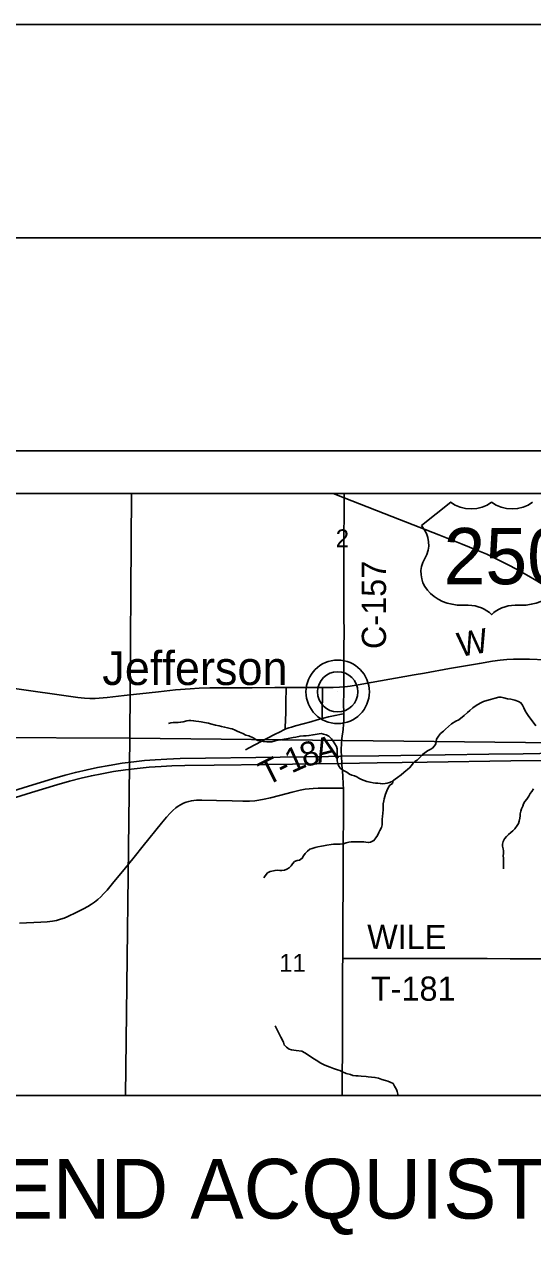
# Model space of a CAD drawing. Extents: x 0 to 34, y 0 to 22.
# Drawn here: x 3.534 to 4.726, y 19.142 to 22 of the extents above; entities that cross this region are included whole.
import ezdxf

# ---------------------------------------------------------------- set-up
doc = ezdxf.new("R2010")
doc.units = 0
for name, color, linetype in [('GM_X_County_Road', 7, 'Continuous'), ('GM_X_County_Road_Text', 7, 'Continuous'), ('GM_X_Minor_River', 7, 'Continuous'), ('GM_X_Section', 7, 'Continuous'), ('GM_X_Section_Text', 7, 'Continuous'), ('GM_X_Township_Road', 7, 'Continuous'), ('GM_X_Township_Road_Text', 7, 'Continuous'), ('GM_X_Unincorporated', 7, 'Continuous'), ('GM_X_Unincorporated_Location', 7, 'Continuous'), ('GM_X_Unincorporated_Text', 7, 'Continuous'), ('GM_X_US_Location', 7, 'Continuous'), ('GM_X_US_Route', 7, 'Continuous'), ('GM_X_US_Shield', 7, 'Continuous'), ('SH_Border', 7, 'Continuous'), ('SH_Cut_Line', 7, 'Continuous'), ('SH_Data', 7, 'Continuous'), ('SH_Text', 7, 'Continuous')]:
    doc.layers.add(name, color=color, linetype=linetype)

msp = doc.modelspace()

# ---------------------------------------------------------------- linework, layer by layer
at = {"layer": 'GM_X_County_Road'}
for points in [[(4.283, 20.4469), (4.283, 20.4533), (4.283, 20.4583), (4.2832, 20.4747), (4.2833, 20.4999), (4.2836, 20.5329), (4.2837, 20.5808), (4.2835, 20.6068), (4.2836, 20.6293), (4.2835, 20.6604), (4.2834, 20.7476), (4.2834, 20.7799), (4.2836, 20.8036), (4.2836, 20.8223), (4.2837, 20.8316), (4.2837, 20.8378), (4.2838, 20.8472), (4.2838, 20.8752), (4.2837, 20.8842), (4.2837, 20.89)], [(4.283, 20.4469), (4.286, 20.4472), (4.2983, 20.4487), (4.3168, 20.4517), (4.3473, 20.4574), (4.4482, 20.4752), (4.4727, 20.4795), (4.5308, 20.4898), (4.6012, 20.5021), (4.6318, 20.5072), (4.6503, 20.5097), (4.6657, 20.5113), (4.6812, 20.5121), (4.6967, 20.5123), (4.7184, 20.5117), (4.7556, 20.5101), (4.7757, 20.5094)], [(3.2685, 20.4779), (3.3764, 20.4624), (3.4779, 20.4477), (3.5272, 20.4408), (3.6317, 20.4257), (3.6595, 20.4219), (3.675, 20.4205), (3.6874, 20.4199), (3.6999, 20.4199), (3.7093, 20.4204), (3.7279, 20.4221), (3.768, 20.4266), (3.8483, 20.4356), (3.8885, 20.4397), (3.9225, 20.4425), (3.9442, 20.4437), (3.969, 20.4444), (4.025, 20.445), (4.0684, 20.4451), (4.1212, 20.4452), (4.1482, 20.4454)], [(4.1482, 20.4454), (4.1927, 20.4455), (4.2332, 20.4457)], [(4.2332, 20.4457), (4.258, 20.4458), (4.2735, 20.4463), (4.283, 20.4469)], [(4.2831, 20.3841), (4.2831, 20.3852), (4.2828, 20.4084), (4.2829, 20.433), (4.283, 20.4441), (4.283, 20.4469)], [(4.283, 20.3699), (4.283, 20.3718), (4.2831, 20.3841)], [(4.2785, 20.2677), (4.2778, 20.2842), (4.2777, 20.2859), (4.2773, 20.2958), (4.2773, 20.3011), (4.2777, 20.3134), (4.2787, 20.3257), (4.2814, 20.3471), (4.2826, 20.3595), (4.283, 20.3699)], [(4.2822, 20.2099), (4.282, 20.2176), (4.2807, 20.2393), (4.2787, 20.2641), (4.2785, 20.2677)], [(3.5225, 19.8929), (3.5722, 19.8953), (3.5878, 19.8965), (3.6001, 19.898), (3.6092, 19.8997), (3.6185, 19.9021), (3.6274, 19.905), (3.636, 19.9087), (3.6557, 19.9181), (3.6723, 19.9264), (3.6831, 19.9323), (3.6912, 19.9374), (3.6987, 19.9425), (3.7061, 19.9484), (3.713, 19.9547), (3.7195, 19.9615), (3.7279, 19.9708), (3.7436, 19.99), (3.7677, 20.0188), (3.7913, 20.0476), (3.8128, 20.0742), (3.8559, 20.1273), (3.8675, 20.1414), (3.8759, 20.1508), (3.8823, 20.1574), (3.8894, 20.1633), (3.8947, 20.167), (3.8999, 20.1702), (3.9073, 20.1742), (3.9138, 20.1768), (3.9196, 20.1786), (3.9256, 20.18), (3.9317, 20.1809), (3.9378, 20.1814), (3.9502, 20.1816), (3.9843, 20.1808), (4.0216, 20.1798), (4.0463, 20.1791), (4.062, 20.1792), (4.0744, 20.1799), (4.0837, 20.1811), (4.0963, 20.1834), (4.1111, 20.1866), (4.1322, 20.1922), (4.1624, 20.1999), (4.1806, 20.2045), (4.1926, 20.2069), (4.2018, 20.2082), (4.211, 20.2091), (4.2234, 20.2097), (4.242, 20.2099), (4.2606, 20.2098), (4.2794, 20.2099), (4.2822, 20.2099)], [(4.2825, 20.185), (4.2825, 20.1989), (4.2822, 20.2099)], [(4.2806, 19.8102), (4.2806, 19.8168), (4.281, 19.8821), (4.2809, 19.91), (4.2814, 19.9753), (4.2818, 20.0281), (4.2819, 20.0809), (4.2823, 20.1399), (4.2826, 20.1741), (4.2825, 20.185)], [(4.2792, 19.4891), (4.2792, 19.5031), (4.2794, 19.5186), (4.2797, 19.5434), (4.28, 19.5838), (4.2802, 19.6087), (4.2801, 19.6428), (4.2801, 19.6832), (4.2805, 19.7671), (4.2805, 19.7889), (4.2806, 19.8102)]]:
    msp.add_lwpolyline(points, dxfattribs=at)
at = {"layer": 'GM_X_Minor_River'}
for points in [[(4.7337, 20.3558), (4.7223, 20.3702), (4.7169, 20.3777), (4.7123, 20.3849), (4.7085, 20.3906), (4.7058, 20.3978), (4.7024, 20.4043), (4.6985, 20.4096), (4.6928, 20.413), (4.6841, 20.4156), (4.6753, 20.4178), (4.6674, 20.4193), (4.6583, 20.4212), (4.6525, 20.4227), (4.6465, 20.423), (4.6381, 20.4207), (4.6325, 20.4188), (4.6275, 20.4176), (4.6188, 20.4153), (4.6112, 20.4126), (4.6029, 20.4088), (4.5938, 20.4034), (4.5859, 20.3977), (4.5787, 20.3919), (4.5734, 20.3873), (4.5655, 20.3801), (4.5534, 20.3701), (4.5462, 20.3663), (4.536, 20.3606), (4.5288, 20.3541), (4.522, 20.3476), (4.5167, 20.3434), (4.5103, 20.338), (4.505, 20.3311), (4.5009, 20.3247), (4.4998, 20.3193), (4.4987, 20.3136), (4.496, 20.3087), (4.4911, 20.3033), (4.4854, 20.2999), (4.4798, 20.2968), (4.473, 20.2926), (4.4677, 20.2888), (4.4613, 20.2815), (4.4552, 20.2754), (4.4503, 20.2727), (4.4458, 20.2678), (4.442, 20.2628), (4.4371, 20.2574), (4.4239, 20.246), (4.4174, 20.241), (4.4095, 20.2349), (4.4035, 20.2303), (4.3967, 20.2253), (4.3902, 20.2226), (4.3853, 20.2215), (4.38, 20.2203), (4.375, 20.2195), (4.3686, 20.2206), (4.3629, 20.2214), (4.3572, 20.2213), (4.3523, 20.2221), (4.345, 20.2236), (4.3374, 20.2254), (4.3306, 20.2273), (4.3249, 20.2296), (4.3188, 20.2333), (4.3139, 20.2363), (4.3082, 20.2382), (4.3017, 20.2401), (4.2964, 20.2424), (4.2907, 20.2469), (4.2853, 20.2495), (4.2804, 20.2525), (4.275, 20.2563), (4.2708, 20.2624), (4.2689, 20.2677), (4.2677, 20.2734), (4.2677, 20.2818), (4.2673, 20.2875), (4.2676, 20.2943), (4.268, 20.3015), (4.266, 20.3076), (4.2618, 20.3133), (4.258, 20.3197), (4.2546, 20.325)], [(4.2546, 20.325), (4.2481, 20.3311), (4.2416, 20.3345), (4.2352, 20.3364), (4.2298, 20.3375), (4.2211, 20.3363), (4.2113, 20.3347), (4.2014, 20.3328), (4.1953, 20.3324), (4.1889, 20.3324), (4.1805, 20.3316), (4.1707, 20.3292), (4.1642, 20.3281), (4.1566, 20.3265), (4.1491, 20.3253), (4.143, 20.3242), (4.1358, 20.3226), (4.1293, 20.3218), (4.1225, 20.3203), (4.1142, 20.3183), (4.1077, 20.3179), (4.1024, 20.3183), (4.0944, 20.319), (4.0887, 20.3201), (4.0819, 20.3216), (4.0766, 20.3235), (4.0709, 20.3272), (4.0602, 20.3321), (4.0538, 20.334), (4.0461, 20.3378), (4.0382, 20.3408), (4.0332, 20.343), (4.0283, 20.3457), (4.0214, 20.3483), (4.0165, 20.3498), (4.0104, 20.3513), (4.0036, 20.3528), (3.9963, 20.3543), (3.991, 20.3558), (3.9819, 20.3576), (3.9709, 20.3602), (3.9659, 20.3617), (3.961, 20.3629), (3.9561, 20.3636), (3.9485, 20.3651), (3.9432, 20.3658), (3.9363, 20.3666), (3.931, 20.3677), (3.9245, 20.368), (3.9196, 20.3684), (3.9147, 20.3676), (3.9063, 20.3653), (3.9003, 20.3641), (3.8946, 20.3637), (3.8836, 20.3637), (3.8775, 20.3625), (3.8718, 20.3613)], [(4.3991, 20.2271), (4.3971, 20.2208), (4.3914, 20.2162), (4.3872, 20.2105), (4.3839, 20.2032), (4.3809, 20.1952), (4.3794, 20.1903), (4.3779, 20.1846), (4.3768, 20.1796), (4.3757, 20.1728), (4.3753, 20.1659), (4.3754, 20.1591), (4.375, 20.1511), (4.3739, 20.1431), (4.3732, 20.1366), (4.3732, 20.1305), (4.3733, 20.1233), (4.3714, 20.1172), (4.368, 20.1104), (4.365, 20.1054), (4.3624, 20.0986), (4.3586, 20.0928), (4.3537, 20.0871), (4.3458, 20.0833), (4.3405, 20.0821), (4.3352, 20.0828), (4.3298, 20.084), (4.3052, 20.0838), (4.3002, 20.0838), (4.2953, 20.083), (4.2889, 20.0815), (4.2828, 20.0792), (4.2748, 20.078), (4.2676, 20.0784), (4.2593, 20.0779), (4.2532, 20.0771), (4.2437, 20.0756), (4.2358, 20.0744), (4.2308, 20.0732), (4.2225, 20.0717), (4.2157, 20.0701), (4.2089, 20.0682), (4.2039, 20.0663), (4.1979, 20.0621), (4.1922, 20.0563), (4.1888, 20.0506), (4.1858, 20.0453), (4.179, 20.0411), (4.1741, 20.0399), (4.1676, 20.0376), (4.1631, 20.0322), (4.1601, 20.0273), (4.1552, 20.0227), (4.1499, 20.0193), (4.1438, 20.017), (4.1378, 20.0162), (4.1328, 20.0165), (4.1275, 20.0173), (4.1222, 20.0169), (4.1108, 20.0138), (4.1044, 20.0107), (4.0987, 20.0042), (4.0957, 19.9992)], [(4.7281, 20.2082), (4.7239, 20.2017), (4.7205, 20.1968), (4.7171, 20.191), (4.7122, 20.1834), (4.7081, 20.1781), (4.7047, 20.1731), (4.7032, 20.1674), (4.7002, 20.1613), (4.6983, 20.156), (4.6972, 20.1495), (4.6969, 20.1446), (4.6962, 20.1389), (4.6947, 20.132), (4.6928, 20.1271), (4.6898, 20.1217), (4.6845, 20.1145), (4.68, 20.1095), (4.6751, 20.1053), (4.6698, 20.1011), (4.6645, 20.0961), (4.66, 20.0904), (4.657, 20.0843), (4.6555, 20.0786), (4.6551, 20.0737), (4.6567, 20.0676), (4.6575, 20.0623), (4.6575, 20.0566), (4.6571, 20.0512), (4.6576, 20.0455), (4.658, 20.0387), (4.6576, 20.0326), (4.658, 20.0258), (4.6577, 20.0201)], [(4.131, 19.6355), (4.1253, 19.6458), (4.1222, 19.6522)], [(4.411, 19.4891), (4.408, 19.4984), (4.4065, 19.5033), (4.4023, 19.5113), (4.3988, 19.517), (4.3916, 19.5204), (4.3867, 19.523), (4.381, 19.5241), (4.3722, 19.5268), (4.3646, 19.5298), (4.3563, 19.5316), (4.3407, 19.5331), (4.3354, 19.5338), (4.3236, 19.5341), (4.3172, 19.5349), (4.3115, 19.5352), (4.3046, 19.536), (4.2989, 19.5386), (4.289, 19.5404), (4.2799, 19.5446), (4.2738, 19.548), (4.2685, 19.5491), (4.259, 19.5525), (4.251, 19.5555), (4.2453, 19.5577), (4.2385, 19.5604), (4.2274, 19.5656), (4.2221, 19.5694), (4.2107, 19.5766), (4.2027, 19.5823), (4.192, 19.5891), (4.1848, 19.5932), (4.1711, 19.5943), (4.1662, 19.595), (4.1609, 19.5958), (4.1551, 19.598), (4.1487, 19.6022), (4.1433, 19.6078), (4.1414, 19.6143), (4.1353, 19.6257), (4.131, 19.6355)]]:
    msp.add_lwpolyline(points, dxfattribs=at)
at = {"layer": 'GM_X_Section'}
for points in [[(3.7715, 19.4891), (3.7817, 20.3267), (2.7459, 20.3315), (2.736, 19.3101), (3.1951, 19.3083), (3.1951, 19.4891)], [(4.783, 19.4891), (4.7808, 20.316), (3.7817, 20.3267), (3.7715, 19.4891)]]:
    msp.add_lwpolyline(points, close=True, dxfattribs=at)
at = {"layer": 'GM_X_Township_Road'}
msp.add_line((4.2837, 20.89), (4.2837, 20.9), dxfattribs=at)
for points in [[(5.7818, 20.9), (2.1, 20.9)], [(4.1457, 20.3477), (4.1458, 20.3523), (4.147, 20.3861), (4.1476, 20.42), (4.1478, 20.4354), (4.148, 20.4415), (4.1482, 20.4454)], [(4.2327, 20.373), (4.2325, 20.3779), (4.2325, 20.3836), (4.2326, 20.393), (4.2332, 20.4246), (4.2332, 20.4404), (4.2332, 20.4457)], [(4.2327, 20.373), (4.2356, 20.3738), (4.2476, 20.3769), (4.2627, 20.3802), (4.278, 20.3831), (4.2831, 20.3841)], [(4.1457, 20.3477), (4.1498, 20.3494), (4.154, 20.351), (4.1603, 20.3529), (4.1699, 20.3556), (4.2058, 20.3652), (4.2207, 20.3696), (4.2327, 20.373)], [(4.0528, 20.2997), (4.0609, 20.3041), (4.0747, 20.3111), (4.0912, 20.3197), (4.1187, 20.3342), (4.1352, 20.3427), (4.1412, 20.3457), (4.1457, 20.3477)], [(4.2806, 19.8102), (4.2848, 19.8102), (4.2916, 19.8102), (4.3182, 19.8101), (4.3614, 19.8101), (4.4, 19.8101), (4.4351, 19.8102), (4.4746, 19.8102), (4.5066, 19.81), (4.5778, 19.8103), (4.6194, 19.8102), (4.6735, 19.8097), (4.7077, 19.8097), (4.7546, 19.8097), (4.8159, 19.8101)]]:
    msp.add_lwpolyline(points, dxfattribs=at)
at = {"layer": 'GM_X_Unincorporated'}
for points in [[(3.785, 20.9), (2.7503, 20.9), (2.7459, 20.3315), (3.7817, 20.3267)], [(4.7739, 20.9), (3.785, 20.9), (3.7817, 20.3267), (4.7808, 20.316)]]:
    msp.add_lwpolyline(points, close=True, dxfattribs=at)
for radius in [0.0744, 0.0472]:
    msp.add_circle((4.2689, 20.4353), radius, dxfattribs=at)
at = {"layer": 'GM_X_Unincorporated_Location'}
msp.add_line((4.2689, 20.4353), (4.2689, 20.4353), dxfattribs=at)
at = {"layer": 'GM_X_US_Route'}
for points in [[(4.258, 20.9), (4.2837, 20.89), (4.4135, 20.8396), (4.4602, 20.8211), (4.5062, 20.8035), (4.5612, 20.7819), (4.5956, 20.7677), (4.6184, 20.7577), (4.6437, 20.7459), (4.6684, 20.7334), (4.6879, 20.7233), (4.712, 20.7099), (4.7362, 20.6954), (4.7574, 20.6823), (4.772, 20.6725), (4.7766, 20.6695)], [(3.4573, 20.1877), (3.5434, 20.2143), (3.5999, 20.2314), (3.6297, 20.2401), (3.6537, 20.2464), (3.681, 20.2528), (3.7053, 20.2579), (3.7327, 20.263), (3.7634, 20.2679), (3.7911, 20.2716), (3.8158, 20.2743), (3.8406, 20.2763), (3.8685, 20.2779), (3.8995, 20.2789), (3.9585, 20.2796), (4.0766, 20.2813), (4.2475, 20.2838), (4.2753, 20.2842), (4.2778, 20.2842), (4.3656, 20.2854), (4.5209, 20.2877), (4.6235, 20.2889), (4.7043, 20.2901), (4.782, 20.2912)], [(3.4646, 20.1729), (3.5506, 20.1997), (3.6101, 20.2177), (3.6401, 20.2261), (3.6672, 20.2331), (3.6914, 20.2386), (3.7158, 20.2435), (3.7434, 20.2484), (3.7711, 20.2526), (3.7989, 20.256), (3.8267, 20.2587), (3.8547, 20.2607), (3.8795, 20.2618), (3.9106, 20.2626), (3.9789, 20.2636), (4.1063, 20.2654), (4.276, 20.2677), (4.2785, 20.2677), (4.3611, 20.2688), (4.4791, 20.2706), (4.6749, 20.2733), (4.7712, 20.2746)]]:
    msp.add_lwpolyline(points, dxfattribs=at)
at = {"layer": 'GM_X_US_Shield'}
for p, q in [((4.5339, 20.8799), (4.4652, 20.8249)), ((4.5613, 20.6382), (4.5751, 20.6382)), ((4.6849, 20.6382), (4.6986, 20.6382))]:
    msp.add_line(p, q, dxfattribs=at)
for centre, major_axis, start_param, end_param in [((4.5819, 20.9191), (-0.0687, 0), 0.795399, 2.346194), ((4.678, 20.9191), (-0.0687, 0), 0.795399, 2.346194), ((4.3864, 20.7808), (0.0961, 0), 5.838949, 6.894067), ((4.5602, 20.7151), (0.0961, 0), 2.702327, 4.723529), ((4.6997, 20.7151), (-0.0961, 0), 1.559657, 3.580859), ((4.5751, 20.5832), (-0.0687, 0), 3.785094, 4.712389), ((4.6849, 20.5832), (-0.0687, 0), 4.712389, 5.639684)]:
    msp.add_ellipse(centre, major_axis=major_axis, ratio=0.8, start_param=start_param, end_param=end_param, dxfattribs=at)
at = {"layer": 'SH_Border'}
msp.add_lwpolyline([(1.5, 21.5), (33.5, 21.5), (33.5, 0.5), (1.5, 0.5)], close=True, dxfattribs=at)
at = {"layer": 'SH_Cut_Line'}
msp.add_lwpolyline([(0, 0), (34, 0), (34, 22), (0, 22)], close=True, dxfattribs=at)
at = {"layer": 'SH_Data'}
for p, q in [((2, 21), (9, 21)), ((2.1, 20.9), (8.9, 20.9))]:
    msp.add_line(p, q, dxfattribs=at)
at = {"layer": 'SH_Text'}
msp.add_lwpolyline([(3.1951, 19.4891), (5.415, 19.4891), (5.415, 18.772), (3.1951, 18.772)], close=True, dxfattribs=at)

# ---------------------------------------------------------------- texts
at = {"layer": 'GM_X_County_Road_Text'}
for s, height, rotation, p in [('C-157', 0.05682, 90, (4.3822, 20.5356)), ('W', 0.0568, 10.0486, (4.5546, 20.5168))]:
    msp.add_text(s, height=height, rotation=rotation, dxfattribs=at).set_placement(p)
at = {"layer": 'GM_X_Section_Text'}
for s, height, p in [('2', 0.0419, (4.2643, 20.7743)), ('11', 0.04186, (4.1318, 19.779))]:
    msp.add_text(s, height=height, rotation=0, dxfattribs=at).set_placement(p)
at = {"layer": 'GM_X_Township_Road_Text'}
for s, height, rotation, p in [('A', 0.0568, 14.4674, (4.2235, 20.2677)), ('1', 0.0568, 24.1812, (4.1606, 20.2436)), ('8', 0.0568, 17.5175, (4.1909, 20.2574)), ('T', 0.0568, 26.9445, (4.1025, 20.2143)), ('-', 0.0568, 26.394, (4.1402, 20.2335)), ('WILE', 0.05682, 359.7262, (4.3378, 19.833)), ('T-181', 0.05682, 0, (4.3468, 19.7112))]:
    msp.add_text(s, height=height, rotation=rotation, dxfattribs=at).set_placement(p)
at = {"layer": 'GM_X_Unincorporated_Text'}
msp.add_text('Jefferson', height=0.07898, rotation=0, dxfattribs=at).set_placement((3.7168, 20.4514))
at = {"layer": 'GM_X_US_Location'}
for s in ['0', '/']:
    msp.add_text(s, height=0.000189, dxfattribs=at).set_placement((4.6301, 20.7534))
msp.add_text('250', height=0.000189, rotation=0, dxfattribs=at).set_placement((4.5718, 20.7142))
at = {"layer": 'GM_X_US_Shield'}
msp.add_text('250', height=0.13184, dxfattribs=at).set_placement((4.5172, 20.6876))
at = {"layer": 'SH_Text'}
msp.add_text('END ACQUISTION', height=0.14, dxfattribs=at).set_placement((3.4761, 19.2005))

doc.saveas('drawing.dxf')
